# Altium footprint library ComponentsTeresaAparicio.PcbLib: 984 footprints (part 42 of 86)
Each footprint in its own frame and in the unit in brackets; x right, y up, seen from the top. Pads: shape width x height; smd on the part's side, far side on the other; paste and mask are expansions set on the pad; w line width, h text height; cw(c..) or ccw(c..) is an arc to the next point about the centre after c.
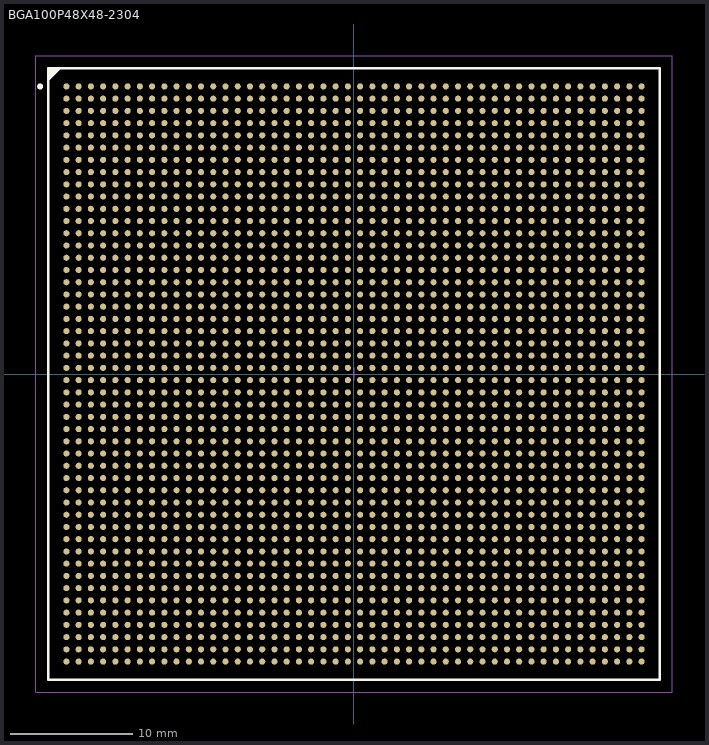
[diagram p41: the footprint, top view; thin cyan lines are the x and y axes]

## BGA100P48X48-2304 [mm] "BGA, 2304-Leads, Body 50x50mm, Pitch 1mm"
height 3.5
pads (2304):
  round 0.5 smd: A1(-23.5,23.5) A2(-22.5,23.5) A3(-21.5,23.5) A4(-20.5,23.5) A5(-19.5,23.5) A6(-18.5,23.5) A7(-17.5,23.5) A8(-16.5,23.5) A9(-15.5,23.5) A10(-14.5,23.5) A11(-13.5,23.5) A12(-12.5,23.5) A13(-11.5,23.5) A14(-10.5,23.5) A15(-9.5,23.5) A16(-8.5,23.5) A17(-7.5,23.5) A18(-6.5,23.5) A19(-5.5,23.5) A20(-4.5,23.5) A21(-3.5,23.5) A22(-2.5,23.5) A23(-1.5,23.5) A24(-0.5,23.5) A25(0.5,23.5) A26(1.5,23.5) A27(2.5,23.5) A28(3.5,23.5) A29(4.5,23.5) A30(5.5,23.5) A31(6.5,23.5) A32(7.5,23.5) A33(8.5,23.5) A34(9.5,23.5) A35(10.5,23.5) A36(11.5,23.5) A37(12.5,23.5) A38(13.5,23.5) A39(14.5,23.5) A40(15.5,23.5) A41(16.5,23.5) A42(17.5,23.5) A43(18.5,23.5) A44(19.5,23.5) A45(20.5,23.5) A46(21.5,23.5) A47(22.5,23.5) A48(23.5,23.5) AA1(-23.5,3.5) AA2(-22.5,3.5) AA3(-21.5,3.5) AA4(-20.5,3.5) AA5(-19.5,3.5) AA6(-18.5,3.5) AA7(-17.5,3.5) AA8(-16.5,3.5) AA9(-15.5,3.5) AA10(-14.5,3.5) AA11(-13.5,3.5) AA12(-12.5,3.5) AA13(-11.5,3.5) AA14(-10.5,3.5) AA15(-9.5,3.5) AA16(-8.5,3.5) AA17(-7.5,3.5) AA18(-6.5,3.5) AA19(-5.5,3.5) AA20(-4.5,3.5) AA21(-3.5,3.5) AA22(-2.5,3.5) AA23(-1.5,3.5) AA24(-0.5,3.5) AA25(0.5,3.5) AA26(1.5,3.5) AA27(2.5,3.5) AA28(3.5,3.5) AA29(4.5,3.5) AA30(5.5,3.5) AA31(6.5,3.5) AA32(7.5,3.5) AA33(8.5,3.5) AA34(9.5,3.5) AA35(10.5,3.5) AA36(11.5,3.5) AA37(12.5,3.5) AA38(13.5,3.5) AA39(14.5,3.5) AA40(15.5,3.5) AA41(16.5,3.5) AA42(17.5,3.5) AA43(18.5,3.5) AA44(19.5,3.5) AA45(20.5,3.5) AA46(21.5,3.5) AA47(22.5,3.5) AA48(23.5,3.5) AB1(-23.5,2.5) AB2(-22.5,2.5) AB3(-21.5,2.5) AB4(-20.5,2.5) AB5(-19.5,2.5) AB6(-18.5,2.5) AB7(-17.5,2.5) AB8(-16.5,2.5) AB9(-15.5,2.5) AB10(-14.5,2.5) AB11(-13.5,2.5) AB12(-12.5,2.5) AB13(-11.5,2.5) AB14(-10.5,2.5) AB15(-9.5,2.5) AB16(-8.5,2.5) AB17(-7.5,2.5) AB18(-6.5,2.5) AB19(-5.5,2.5) AB20(-4.5,2.5) AB21(-3.5,2.5) AB22(-2.5,2.5) AB23(-1.5,2.5) AB24(-0.5,2.5) AB25(0.5,2.5) AB26(1.5,2.5) AB27(2.5,2.5) AB28(3.5,2.5) AB29(4.5,2.5) AB30(5.5,2.5) AB31(6.5,2.5) AB32(7.5,2.5) AB33(8.5,2.5) AB34(9.5,2.5) AB35(10.5,2.5) AB36(11.5,2.5) AB37(12.5,2.5) AB38(13.5,2.5) AB39(14.5,2.5) AB40(15.5,2.5) AB41(16.5,2.5) AB42(17.5,2.5) AB43(18.5,2.5) AB44(19.5,2.5) AB45(20.5,2.5) AB46(21.5,2.5) AB47(22.5,2.5) AB48(23.5,2.5) AC1(-23.5,1.5) AC2(-22.5,1.5) AC3(-21.5,1.5) AC4(-20.5,1.5) AC5(-19.5,1.5) AC6(-18.5,1.5) AC7(-17.5,1.5) AC8(-16.5,1.5) AC9(-15.5,1.5) AC10(-14.5,1.5) AC11(-13.5,1.5) AC12(-12.5,1.5) AC13(-11.5,1.5) AC14(-10.5,1.5) AC15(-9.5,1.5) AC16(-8.5,1.5) AC17(-7.5,1.5) AC18(-6.5,1.5) AC19(-5.5,1.5) AC20(-4.5,1.5) AC21(-3.5,1.5) AC22(-2.5,1.5) AC23(-1.5,1.5) AC24(-0.5,1.5) AC25(0.5,1.5) AC26(1.5,1.5) AC27(2.5,1.5) AC28(3.5,1.5) AC29(4.5,1.5) AC30(5.5,1.5) AC31(6.5,1.5) AC32(7.5,1.5) AC33(8.5,1.5) AC34(9.5,1.5) AC35(10.5,1.5) AC36(11.5,1.5) AC37(12.5,1.5) AC38(13.5,1.5) AC39(14.5,1.5) AC40(15.5,1.5) AC41(16.5,1.5) AC42(17.5,1.5) AC43(18.5,1.5) AC44(19.5,1.5) AC45(20.5,1.5) AC46(21.5,1.5) AC47(22.5,1.5) AC48(23.5,1.5) AD1(-23.5,0.5) AD2(-22.5,0.5) AD3(-21.5,0.5) AD4(-20.5,0.5) AD5(-19.5,0.5) AD6(-18.5,0.5) AD7(-17.5,0.5) AD8(-16.5,0.5) AD9(-15.5,0.5) AD10(-14.5,0.5) AD11(-13.5,0.5) AD12(-12.5,0.5) AD13(-11.5,0.5) AD14(-10.5,0.5) AD15(-9.5,0.5) AD16(-8.5,0.5) AD17(-7.5,0.5) AD18(-6.5,0.5) AD19(-5.5,0.5) AD20(-4.5,0.5) AD21(-3.5,0.5) AD22(-2.5,0.5) AD23(-1.5,0.5) AD24(-0.5,0.5) AD25(0.5,0.5) AD26(1.5,0.5) AD27(2.5,0.5) AD28(3.5,0.5) AD29(4.5,0.5) AD30(5.5,0.5) AD31(6.5,0.5) AD32(7.5,0.5) AD33(8.5,0.5) AD34(9.5,0.5) AD35(10.5,0.5) AD36(11.5,0.5) AD37(12.5,0.5) AD38(13.5,0.5) AD39(14.5,0.5) AD40(15.5,0.5) AD41(16.5,0.5) AD42(17.5,0.5) AD43(18.5,0.5) AD44(19.5,0.5) AD45(20.5,0.5) AD46(21.5,0.5) AD47(22.5,0.5) AD48(23.5,0.5) AE1(-23.5,-0.5) AE2(-22.5,-0.5) AE3(-21.5,-0.5) AE4(-20.5,-0.5) AE5(-19.5,-0.5) AE6(-18.5,-0.5) AE7(-17.5,-0.5) AE8(-16.5,-0.5) AE9(-15.5,-0.5) AE10(-14.5,-0.5) AE11(-13.5,-0.5) AE12(-12.5,-0.5) AE13(-11.5,-0.5) AE14(-10.5,-0.5) AE15(-9.5,-0.5) AE16(-8.5,-0.5) AE17(-7.5,-0.5) AE18(-6.5,-0.5) AE19(-5.5,-0.5) AE20(-4.5,-0.5) AE21(-3.5,-0.5) AE22(-2.5,-0.5) AE23(-1.5,-0.5) AE24(-0.5,-0.5) AE25(0.5,-0.5) AE26(1.5,-0.5) AE27(2.5,-0.5) AE28(3.5,-0.5) AE29(4.5,-0.5) AE30(5.5,-0.5) AE31(6.5,-0.5) AE32(7.5,-0.5) AE33(8.5,-0.5) AE34(9.5,-0.5) AE35(10.5,-0.5) AE36(11.5,-0.5) AE37(12.5,-0.5) AE38(13.5,-0.5) AE39(14.5,-0.5) AE40(15.5,-0.5) AE41(16.5,-0.5) AE42(17.5,-0.5) AE43(18.5,-0.5) AE44(19.5,-0.5) AE45(20.5,-0.5) AE46(21.5,-0.5) AE47(22.5,-0.5) AE48(23.5,-0.5) AF1(-23.5,-1.5) AF2(-22.5,-1.5) AF3(-21.5,-1.5) AF4(-20.5,-1.5) AF5(-19.5,-1.5) AF6(-18.5,-1.5) AF7(-17.5,-1.5) AF8(-16.5,-1.5) AF9(-15.5,-1.5) AF10(-14.5,-1.5) AF11(-13.5,-1.5) AF12(-12.5,-1.5) AF13(-11.5,-1.5) AF14(-10.5,-1.5) AF15(-9.5,-1.5) AF16(-8.5,-1.5) AF17(-7.5,-1.5) AF18(-6.5,-1.5) AF19(-5.5,-1.5) AF20(-4.5,-1.5) AF21(-3.5,-1.5) AF22(-2.5,-1.5) AF23(-1.5,-1.5) AF24(-0.5,-1.5) AF25(0.5,-1.5) AF26(1.5,-1.5) AF27(2.5,-1.5) AF28(3.5,-1.5) AF29(4.5,-1.5) AF30(5.5,-1.5) AF31(6.5,-1.5) AF32(7.5,-1.5) AF33(8.5,-1.5) AF34(9.5,-1.5) AF35(10.5,-1.5) AF36(11.5,-1.5) AF37(12.5,-1.5) AF38(13.5,-1.5) AF39(14.5,-1.5) AF40(15.5,-1.5) AF41(16.5,-1.5) AF42(17.5,-1.5) AF43(18.5,-1.5) AF44(19.5,-1.5) AF45(20.5,-1.5) AF46(21.5,-1.5) AF47(22.5,-1.5) AF48(23.5,-1.5) AG1(-23.5,-2.5) AG2(-22.5,-2.5) AG3(-21.5,-2.5) AG4(-20.5,-2.5) AG5(-19.5,-2.5) AG6(-18.5,-2.5) AG7(-17.5,-2.5) AG8(-16.5,-2.5) AG9(-15.5,-2.5) AG10(-14.5,-2.5) AG11(-13.5,-2.5) AG12(-12.5,-2.5) AG13(-11.5,-2.5) AG14(-10.5,-2.5) AG15(-9.5,-2.5) AG16(-8.5,-2.5) AG17(-7.5,-2.5) AG18(-6.5,-2.5) AG19(-5.5,-2.5) AG20(-4.5,-2.5) AG21(-3.5,-2.5) AG22(-2.5,-2.5) AG23(-1.5,-2.5) AG24(-0.5,-2.5) AG25(0.5,-2.5) AG26(1.5,-2.5) AG27(2.5,-2.5) AG28(3.5,-2.5) AG29(4.5,-2.5) AG30(5.5,-2.5) AG31(6.5,-2.5) AG32(7.5,-2.5) AG33(8.5,-2.5) AG34(9.5,-2.5) AG35(10.5,-2.5) AG36(11.5,-2.5) AG37(12.5,-2.5) AG38(13.5,-2.5) AG39(14.5,-2.5) AG40(15.5,-2.5) AG41(16.5,-2.5) AG42(17.5,-2.5) AG43(18.5,-2.5) AG44(19.5,-2.5) AG45(20.5,-2.5) AG46(21.5,-2.5) AG47(22.5,-2.5) AG48(23.5,-2.5) AH1(-23.5,-3.5) AH2(-22.5,-3.5) AH3(-21.5,-3.5) AH4(-20.5,-3.5) AH5(-19.5,-3.5) AH6(-18.5,-3.5) AH7(-17.5,-3.5) AH8(-16.5,-3.5) AH9(-15.5,-3.5) AH10(-14.5,-3.5) AH11(-13.5,-3.5) AH12(-12.5,-3.5) AH13(-11.5,-3.5) AH14(-10.5,-3.5) AH15(-9.5,-3.5) AH16(-8.5,-3.5) AH17(-7.5,-3.5) AH18(-6.5,-3.5) AH19(-5.5,-3.5) AH20(-4.5,-3.5) AH21(-3.5,-3.5) AH22(-2.5,-3.5) AH23(-1.5,-3.5) AH24(-0.5,-3.5) AH25(0.5,-3.5) AH26(1.5,-3.5) AH27(2.5,-3.5) AH28(3.5,-3.5) AH29(4.5,-3.5) AH30(5.5,-3.5) AH31(6.5,-3.5) AH32(7.5,-3.5) AH33(8.5,-3.5) AH34(9.5,-3.5) AH35(10.5,-3.5) AH36(11.5,-3.5) AH37(12.5,-3.5) AH38(13.5,-3.5) AH39(14.5,-3.5) AH40(15.5,-3.5) AH41(16.5,-3.5) AH42(17.5,-3.5) AH43(18.5,-3.5) AH44(19.5,-3.5) AH45(20.5,-3.5) AH46(21.5,-3.5) AH47(22.5,-3.5) AH48(23.5,-3.5) AJ1(-23.5,-4.5) AJ2(-22.5,-4.5) AJ3(-21.5,-4.5) AJ4(-20.5,-4.5) AJ5(-19.5,-4.5) AJ6(-18.5,-4.5) AJ7(-17.5,-4.5) AJ8(-16.5,-4.5) AJ9(-15.5,-4.5) AJ10(-14.5,-4.5) AJ11(-13.5,-4.5) AJ12(-12.5,-4.5) AJ13(-11.5,-4.5) AJ14(-10.5,-4.5) AJ15(-9.5,-4.5) AJ16(-8.5,-4.5) AJ17(-7.5,-4.5) AJ18(-6.5,-4.5) AJ19(-5.5,-4.5) AJ20(-4.5,-4.5) AJ21(-3.5,-4.5) AJ22(-2.5,-4.5) AJ23(-1.5,-4.5) AJ24(-0.5,-4.5) AJ25(0.5,-4.5) AJ26(1.5,-4.5) AJ27(2.5,-4.5) AJ28(3.5,-4.5) AJ29(4.5,-4.5) AJ30(5.5,-4.5) AJ31(6.5,-4.5) AJ32(7.5,-4.5) AJ33(8.5,-4.5) AJ34(9.5,-4.5) AJ35(10.5,-4.5) AJ36(11.5,-4.5) AJ37(12.5,-4.5) AJ38(13.5,-4.5) AJ39(14.5,-4.5) AJ40(15.5,-4.5) AJ41(16.5,-4.5) AJ42(17.5,-4.5) AJ43(18.5,-4.5) AJ44(19.5,-4.5) AJ45(20.5,-4.5) AJ46(21.5,-4.5) AJ47(22.5,-4.5) AJ48(23.5,-4.5) AK1(-23.5,-5.5) AK2(-22.5,-5.5) AK3(-21.5,-5.5) AK4(-20.5,-5.5) AK5(-19.5,-5.5) AK6(-18.5,-5.5) AK7(-17.5,-5.5) AK8(-16.5,-5.5) AK9(-15.5,-5.5) AK10(-14.5,-5.5) AK11(-13.5,-5.5) AK12(-12.5,-5.5) AK13(-11.5,-5.5) AK14(-10.5,-5.5) AK15(-9.5,-5.5) AK16(-8.5,-5.5) AK17(-7.5,-5.5) AK18(-6.5,-5.5) AK19(-5.5,-5.5) AK20(-4.5,-5.5) AK21(-3.5,-5.5) AK22(-2.5,-5.5) AK23(-1.5,-5.5) AK24(-0.5,-5.5) AK25(0.5,-5.5) AK26(1.5,-5.5) AK27(2.5,-5.5) AK28(3.5,-5.5) AK29(4.5,-5.5) AK30(5.5,-5.5) AK31(6.5,-5.5) AK32(7.5,-5.5) AK33(8.5,-5.5) AK34(9.5,-5.5) AK35(10.5,-5.5) AK36(11.5,-5.5) AK37(12.5,-5.5) AK38(13.5,-5.5) AK39(14.5,-5.5) AK40(15.5,-5.5) AK41(16.5,-5.5) AK42(17.5,-5.5) AK43(18.5,-5.5) AK44(19.5,-5.5) AK45(20.5,-5.5) AK46(21.5,-5.5) AK47(22.5,-5.5) AK48(23.5,-5.5) AL1(-23.5,-6.5) AL2(-22.5,-6.5) AL3(-21.5,-6.5) AL4(-20.5,-6.5) AL5(-19.5,-6.5) AL6(-18.5,-6.5) AL7(-17.5,-6.5) AL8(-16.5,-6.5) AL9(-15.5,-6.5) AL10(-14.5,-6.5) AL11(-13.5,-6.5) AL12(-12.5,-6.5) AL13(-11.5,-6.5) AL14(-10.5,-6.5) AL15(-9.5,-6.5) AL16(-8.5,-6.5) AL17(-7.5,-6.5) AL18(-6.5,-6.5) AL19(-5.5,-6.5) AL20(-4.5,-6.5) AL21(-3.5,-6.5) AL22(-2.5,-6.5) AL23(-1.5,-6.5) AL24(-0.5,-6.5) AL25(0.5,-6.5) AL26(1.5,-6.5) AL27(2.5,-6.5) AL28(3.5,-6.5) AL29(4.5,-6.5) AL30(5.5,-6.5) AL31(6.5,-6.5) AL32(7.5,-6.5) AL33(8.5,-6.5) AL34(9.5,-6.5) AL35(10.5,-6.5) AL36(11.5,-6.5) AL37(12.5,-6.5) AL38(13.5,-6.5) AL39(14.5,-6.5) AL40(15.5,-6.5) AL41(16.5,-6.5) AL42(17.5,-6.5) AL43(18.5,-6.5) AL44(19.5,-6.5) AL45(20.5,-6.5) AL46(21.5,-6.5) AL47(22.5,-6.5) AL48(23.5,-6.5) AM1(-23.5,-7.5) AM2(-22.5,-7.5) AM3(-21.5,-7.5) AM4(-20.5,-7.5) AM5(-19.5,-7.5) AM6(-18.5,-7.5) AM7(-17.5,-7.5) AM8(-16.5,-7.5) AM9(-15.5,-7.5) AM10(-14.5,-7.5) AM11(-13.5,-7.5) AM12(-12.5,-7.5) AM13(-11.5,-7.5) AM14(-10.5,-7.5) AM15(-9.5,-7.5) AM16(-8.5,-7.5) AM17(-7.5,-7.5) AM18(-6.5,-7.5) AM19(-5.5,-7.5) AM20(-4.5,-7.5) AM21(-3.5,-7.5) AM22(-2.5,-7.5) AM23(-1.5,-7.5) AM24(-0.5,-7.5) AM25(0.5,-7.5) AM26(1.5,-7.5) AM27(2.5,-7.5) AM28(3.5,-7.5) AM29(4.5,-7.5) AM30(5.5,-7.5) AM31(6.5,-7.5) AM32(7.5,-7.5) AM33(8.5,-7.5) AM34(9.5,-7.5) AM35(10.5,-7.5) AM36(11.5,-7.5) AM37(12.5,-7.5) AM38(13.5,-7.5) AM39(14.5,-7.5) AM40(15.5,-7.5) AM41(16.5,-7.5) AM42(17.5,-7.5) AM43(18.5,-7.5) AM44(19.5,-7.5) AM45(20.5,-7.5) AM46(21.5,-7.5) AM47(22.5,-7.5) AM48(23.5,-7.5) AN1(-23.5,-8.5) AN2(-22.5,-8.5) AN3(-21.5,-8.5) AN4(-20.5,-8.5) AN5(-19.5,-8.5) AN6(-18.5,-8.5) AN7(-17.5,-8.5) AN8(-16.5,-8.5) AN9(-15.5,-8.5) AN10(-14.5,-8.5) AN11(-13.5,-8.5) AN12(-12.5,-8.5) AN13(-11.5,-8.5) AN14(-10.5,-8.5) AN15(-9.5,-8.5) AN16(-8.5,-8.5) AN17(-7.5,-8.5) AN18(-6.5,-8.5) AN19(-5.5,-8.5) AN20(-4.5,-8.5) AN21(-3.5,-8.5) AN22(-2.5,-8.5) AN23(-1.5,-8.5) AN24(-0.5,-8.5) AN25(0.5,-8.5) AN26(1.5,-8.5) AN27(2.5,-8.5) AN28(3.5,-8.5) AN29(4.5,-8.5) AN30(5.5,-8.5) AN31(6.5,-8.5) AN32(7.5,-8.5) AN33(8.5,-8.5) AN34(9.5,-8.5) AN35(10.5,-8.5) AN36(11.5,-8.5) AN37(12.5,-8.5) AN38(13.5,-8.5) AN39(14.5,-8.5) AN40(15.5,-8.5) AN41(16.5,-8.5) AN42(17.5,-8.5) AN43(18.5,-8.5) AN44(19.5,-8.5) AN45(20.5,-8.5) AN46(21.5,-8.5) AN47(22.5,-8.5) AN48(23.5,-8.5) AP1(-23.5,-9.5) AP2(-22.5,-9.5) AP3(-21.5,-9.5) AP4(-20.5,-9.5) AP5(-19.5,-9.5) AP6(-18.5,-9.5) AP7(-17.5,-9.5) AP8(-16.5,-9.5) AP9(-15.5,-9.5) AP10(-14.5,-9.5) AP11(-13.5,-9.5) AP12(-12.5,-9.5) AP13(-11.5,-9.5) AP14(-10.5,-9.5) AP15(-9.5,-9.5) AP16(-8.5,-9.5) AP17(-7.5,-9.5) AP18(-6.5,-9.5) AP19(-5.5,-9.5) AP20(-4.5,-9.5) AP21(-3.5,-9.5) AP22(-2.5,-9.5) AP23(-1.5,-9.5) AP24(-0.5,-9.5) AP25(0.5,-9.5) AP26(1.5,-9.5) AP27(2.5,-9.5) AP28(3.5,-9.5) AP29(4.5,-9.5) AP30(5.5,-9.5) AP31(6.5,-9.5) AP32(7.5,-9.5) AP33(8.5,-9.5) AP34(9.5,-9.5) AP35(10.5,-9.5) AP36(11.5,-9.5) AP37(12.5,-9.5) AP38(13.5,-9.5) AP39(14.5,-9.5) AP40(15.5,-9.5) AP41(16.5,-9.5) AP42(17.5,-9.5) AP43(18.5,-9.5) AP44(19.5,-9.5) AP45(20.5,-9.5) AP46(21.5,-9.5) AP47(22.5,-9.5) AP48(23.5,-9.5) AR1(-23.5,-10.5) AR2(-22.5,-10.5) AR3(-21.5,-10.5) AR4(-20.5,-10.5) AR5(-19.5,-10.5) AR6(-18.5,-10.5) AR7(-17.5,-10.5) AR8(-16.5,-10.5) AR9(-15.5,-10.5) AR10(-14.5,-10.5) AR11(-13.5,-10.5) AR12(-12.5,-10.5) AR13(-11.5,-10.5) AR14(-10.5,-10.5) AR15(-9.5,-10.5) AR16(-8.5,-10.5) AR17(-7.5,-10.5) AR18(-6.5,-10.5) AR19(-5.5,-10.5) AR20(-4.5,-10.5) AR21(-3.5,-10.5) AR22(-2.5,-10.5) AR23(-1.5,-10.5) AR24(-0.5,-10.5) AR25(0.5,-10.5) AR26(1.5,-10.5) AR27(2.5,-10.5) AR28(3.5,-10.5) AR29(4.5,-10.5) AR30(5.5,-10.5) AR31(6.5,-10.5) AR32(7.5,-10.5) AR33(8.5,-10.5) AR34(9.5,-10.5) AR35(10.5,-10.5) AR36(11.5,-10.5) AR37(12.5,-10.5) AR38(13.5,-10.5) AR39(14.5,-10.5) AR40(15.5,-10.5) AR41(16.5,-10.5) AR42(17.5,-10.5) AR43(18.5,-10.5) AR44(19.5,-10.5) AR45(20.5,-10.5) AR46(21.5,-10.5) AR47(22.5,-10.5) AR48(23.5,-10.5) AT1(-23.5,-11.5) AT2(-22.5,-11.5) AT3(-21.5,-11.5) AT4(-20.5,-11.5) AT5(-19.5,-11.5) AT6(-18.5,-11.5) AT7(-17.5,-11.5) AT8(-16.5,-11.5) AT9(-15.5,-11.5) AT10(-14.5,-11.5) AT11(-13.5,-11.5) AT12(-12.5,-11.5) AT13(-11.5,-11.5) AT14(-10.5,-11.5) AT15(-9.5,-11.5) AT16(-8.5,-11.5) AT17(-7.5,-11.5) AT18(-6.5,-11.5) AT19(-5.5,-11.5) AT20(-4.5,-11.5) AT21(-3.5,-11.5) AT22(-2.5,-11.5) AT23(-1.5,-11.5) AT24(-0.5,-11.5) AT25(0.5,-11.5) AT26(1.5,-11.5) AT27(2.5,-11.5) AT28(3.5,-11.5) AT29(4.5,-11.5) AT30(5.5,-11.5) AT31(6.5,-11.5) AT32(7.5,-11.5) AT33(8.5,-11.5) AT34(9.5,-11.5) AT35(10.5,-11.5) AT36(11.5,-11.5) AT37(12.5,-11.5) AT38(13.5,-11.5) AT39(14.5,-11.5) AT40(15.5,-11.5) AT41(16.5,-11.5) AT42(17.5,-11.5) AT43(18.5,-11.5) AT44(19.5,-11.5) AT45(20.5,-11.5) AT46(21.5,-11.5) AT47(22.5,-11.5) AT48(23.5,-11.5) AU1(-23.5,-12.5) AU2(-22.5,-12.5) AU3(-21.5,-12.5) AU4(-20.5,-12.5) AU5(-19.5,-12.5) AU6(-18.5,-12.5) AU7(-17.5,-12.5) AU8(-16.5,-12.5) AU9(-15.5,-12.5) AU10(-14.5,-12.5) AU11(-13.5,-12.5) AU12(-12.5,-12.5) AU13(-11.5,-12.5) AU14(-10.5,-12.5) AU15(-9.5,-12.5) AU16(-8.5,-12.5) AU17(-7.5,-12.5) AU18(-6.5,-12.5) AU19(-5.5,-12.5) AU20(-4.5,-12.5) AU21(-3.5,-12.5) AU22(-2.5,-12.5) AU23(-1.5,-12.5) AU24(-0.5,-12.5) AU25(0.5,-12.5) AU26(1.5,-12.5) AU27(2.5,-12.5) AU28(3.5,-12.5) AU29(4.5,-12.5) AU30(5.5,-12.5) AU31(6.5,-12.5) AU32(7.5,-12.5) AU33(8.5,-12.5) AU34(9.5,-12.5) AU35(10.5,-12.5) AU36(11.5,-12.5) AU37(12.5,-12.5) AU38(13.5,-12.5) AU39(14.5,-12.5) AU40(15.5,-12.5) AU41(16.5,-12.5) AU42(17.5,-12.5) AU43(18.5,-12.5) AU44(19.5,-12.5) AU45(20.5,-12.5) AU46(21.5,-12.5) AU47(22.5,-12.5) AU48(23.5,-12.5) AV1(-23.5,-13.5) AV2(-22.5,-13.5) AV3(-21.5,-13.5) AV4(-20.5,-13.5) AV5(-19.5,-13.5) AV6(-18.5,-13.5) AV7(-17.5,-13.5) AV8(-16.5,-13.5) AV9(-15.5,-13.5) AV10(-14.5,-13.5) AV11(-13.5,-13.5) AV12(-12.5,-13.5) AV13(-11.5,-13.5) AV14(-10.5,-13.5) AV15(-9.5,-13.5) AV16(-8.5,-13.5) AV17(-7.5,-13.5) AV18(-6.5,-13.5) AV19(-5.5,-13.5) AV20(-4.5,-13.5) AV21(-3.5,-13.5) AV22(-2.5,-13.5) AV23(-1.5,-13.5) AV24(-0.5,-13.5) AV25(0.5,-13.5) AV26(1.5,-13.5) AV27(2.5,-13.5) AV28(3.5,-13.5) AV29(4.5,-13.5) AV30(5.5,-13.5) AV31(6.5,-13.5) AV32(7.5,-13.5) AV33(8.5,-13.5) AV34(9.5,-13.5) AV35(10.5,-13.5) AV36(11.5,-13.5) AV37(12.5,-13.5) AV38(13.5,-13.5) AV39(14.5,-13.5) AV40(15.5,-13.5) AV41(16.5,-13.5) AV42(17.5,-13.5) AV43(18.5,-13.5) AV44(19.5,-13.5) AV45(20.5,-13.5) AV46(21.5,-13.5) AV47(22.5,-13.5) AV48(23.5,-13.5) AW1(-23.5,-14.5) AW2(-22.5,-14.5) AW3(-21.5,-14.5) AW4(-20.5,-14.5) AW5(-19.5,-14.5) AW6(-18.5,-14.5) AW7(-17.5,-14.5) AW8(-16.5,-14.5) AW9(-15.5,-14.5) AW10(-14.5,-14.5) AW11(-13.5,-14.5) AW12(-12.5,-14.5) AW13(-11.5,-14.5) AW14(-10.5,-14.5) AW15(-9.5,-14.5) AW16(-8.5,-14.5) AW17(-7.5,-14.5) AW18(-6.5,-14.5) AW19(-5.5,-14.5) AW20(-4.5,-14.5) AW21(-3.5,-14.5) AW22(-2.5,-14.5) AW23(-1.5,-14.5) AW24(-0.5,-14.5) AW25(0.5,-14.5) AW26(1.5,-14.5) AW27(2.5,-14.5) AW28(3.5,-14.5) AW29(4.5,-14.5) AW30(5.5,-14.5) AW31(6.5,-14.5) AW32(7.5,-14.5) AW33(8.5,-14.5) AW34(9.5,-14.5) AW35(10.5,-14.5) AW36(11.5,-14.5) AW37(12.5,-14.5) AW38(13.5,-14.5) AW39(14.5,-14.5) AW40(15.5,-14.5) AW41(16.5,-14.5) AW42(17.5,-14.5) AW43(18.5,-14.5) AW44(19.5,-14.5) AW45(20.5,-14.5) AW46(21.5,-14.5) AW47(22.5,-14.5) AW48(23.5,-14.5) AY1(-23.5,-15.5) AY2(-22.5,-15.5) AY3(-21.5,-15.5) AY4(-20.5,-15.5) AY5(-19.5,-15.5) AY6(-18.5,-15.5) AY7(-17.5,-15.5) AY8(-16.5,-15.5) AY9(-15.5,-15.5) AY10(-14.5,-15.5) AY11(-13.5,-15.5) AY12(-12.5,-15.5) AY13(-11.5,-15.5) AY14(-10.5,-15.5) AY15(-9.5,-15.5) AY16(-8.5,-15.5) AY17(-7.5,-15.5) AY18(-6.5,-15.5) AY19(-5.5,-15.5) AY20(-4.5,-15.5) AY21(-3.5,-15.5) AY22(-2.5,-15.5) AY23(-1.5,-15.5) AY24(-0.5,-15.5) AY25(0.5,-15.5) AY26(1.5,-15.5) AY27(2.5,-15.5) AY28(3.5,-15.5) AY29(4.5,-15.5) AY30(5.5,-15.5) AY31(6.5,-15.5) AY32(7.5,-15.5) AY33(8.5,-15.5) AY34(9.5,-15.5) AY35(10.5,-15.5) AY36(11.5,-15.5) AY37(12.5,-15.5) AY38(13.5,-15.5) AY39(14.5,-15.5) AY40(15.5,-15.5) AY41(16.5,-15.5) AY42(17.5,-15.5) AY43(18.5,-15.5) AY44(19.5,-15.5) AY45(20.5,-15.5) AY46(21.5,-15.5) AY47(22.5,-15.5) AY48(23.5,-15.5) B1(-23.5,22.5) B2(-22.5,22.5) B3(-21.5,22.5) B4(-20.5,22.5) B5(-19.5,22.5) B6(-18.5,22.5) B7(-17.5,22.5) B8(-16.5,22.5) B9(-15.5,22.5) B10(-14.5,22.5) B11(-13.5,22.5) B12(-12.5,22.5) B13(-11.5,22.5) B14(-10.5,22.5) B15(-9.5,22.5) B16(-8.5,22.5) B17(-7.5,22.5) B18(-6.5,22.5) B19(-5.5,22.5) B20(-4.5,22.5) B21(-3.5,22.5) B22(-2.5,22.5) B23(-1.5,22.5) B24(-0.5,22.5) B25(0.5,22.5) B26(1.5,22.5) B27(2.5,22.5) B28(3.5,22.5) B29(4.5,22.5) B30(5.5,22.5) B31(6.5,22.5) B32(7.5,22.5) B33(8.5,22.5) B34(9.5,22.5) B35(10.5,22.5) B36(11.5,22.5) B37(12.5,22.5) B38(13.5,22.5) B39(14.5,22.5) B40(15.5,22.5) B41(16.5,22.5) B42(17.5,22.5) B43(18.5,22.5) B44(19.5,22.5) B45(20.5,22.5) B46(21.5,22.5) B47(22.5,22.5) B48(23.5,22.5) BA1(-23.5,-16.5) BA2(-22.5,-16.5) BA3(-21.5,-16.5) BA4(-20.5,-16.5) BA5(-19.5,-16.5) BA6(-18.5,-16.5) BA7(-17.5,-16.5) BA8(-16.5,-16.5) BA9(-15.5,-16.5) BA10(-14.5,-16.5) BA11(-13.5,-16.5) BA12(-12.5,-16.5) BA13(-11.5,-16.5) BA14(-10.5,-16.5) BA15(-9.5,-16.5) BA16(-8.5,-16.5) BA17(-7.5,-16.5) BA18(-6.5,-16.5) BA19(-5.5,-16.5) BA20(-4.5,-16.5) BA21(-3.5,-16.5) BA22(-2.5,-16.5) BA23(-1.5,-16.5) BA24(-0.5,-16.5) BA25(0.5,-16.5) BA26(1.5,-16.5) BA27(2.5,-16.5) BA28(3.5,-16.5) BA29(4.5,-16.5) BA30(5.5,-16.5) BA31(6.5,-16.5) BA32(7.5,-16.5) BA33(8.5,-16.5) BA34(9.5,-16.5) BA35(10.5,-16.5) BA36(11.5,-16.5) BA37(12.5,-16.5) BA38(13.5,-16.5) BA39(14.5,-16.5) BA40(15.5,-16.5) BA41(16.5,-16.5) BA42(17.5,-16.5) BA43(18.5,-16.5) BA44(19.5,-16.5) BA45(20.5,-16.5) BA46(21.5,-16.5) BA47(22.5,-16.5) BA48(23.5,-16.5) BB1(-23.5,-17.5) BB2(-22.5,-17.5) BB3(-21.5,-17.5) BB4(-20.5,-17.5) BB5(-19.5,-17.5) BB6(-18.5,-17.5) BB7(-17.5,-17.5) BB8(-16.5,-17.5) BB9(-15.5,-17.5) BB10(-14.5,-17.5) BB11(-13.5,-17.5) BB12(-12.5,-17.5) BB13(-11.5,-17.5) BB14(-10.5,-17.5) BB15(-9.5,-17.5) BB16(-8.5,-17.5) BB17(-7.5,-17.5) BB18(-6.5,-17.5) BB19(-5.5,-17.5) BB20(-4.5,-17.5) BB21(-3.5,-17.5) BB22(-2.5,-17.5) BB23(-1.5,-17.5) BB24(-0.5,-17.5) BB25(0.5,-17.5) BB26(1.5,-17.5) BB27(2.5,-17.5) BB28(3.5,-17.5) BB29(4.5,-17.5) BB30(5.5,-17.5) BB31(6.5,-17.5) BB32(7.5,-17.5) BB33(8.5,-17.5) BB34(9.5,-17.5) BB35(10.5,-17.5) BB36(11.5,-17.5) BB37(12.5,-17.5) BB38(13.5,-17.5) BB39(14.5,-17.5) BB40(15.5,-17.5) BB41(16.5,-17.5) BB42(17.5,-17.5) BB43(18.5,-17.5) BB44(19.5,-17.5) BB45(20.5,-17.5) BB46(21.5,-17.5) BB47(22.5,-17.5) BB48(23.5,-17.5) BC1(-23.5,-18.5) BC2(-22.5,-18.5) BC3(-21.5,-18.5) BC4(-20.5,-18.5) BC5(-19.5,-18.5) BC6(-18.5,-18.5) BC7(-17.5,-18.5) BC8(-16.5,-18.5) BC9(-15.5,-18.5) BC10(-14.5,-18.5) BC11(-13.5,-18.5) BC12(-12.5,-18.5) BC13(-11.5,-18.5) BC14(-10.5,-18.5) BC15(-9.5,-18.5) BC16(-8.5,-18.5) BC17(-7.5,-18.5) BC18(-6.5,-18.5) BC19(-5.5,-18.5) BC20(-4.5,-18.5) BC21(-3.5,-18.5) BC22(-2.5,-18.5) BC23(-1.5,-18.5) BC24(-0.5,-18.5) BC25(0.5,-18.5) BC26(1.5,-18.5) BC27(2.5,-18.5) BC28(3.5,-18.5) BC29(4.5,-18.5) BC30(5.5,-18.5) BC31(6.5,-18.5) BC32(7.5,-18.5) BC33(8.5,-18.5) BC34(9.5,-18.5) BC35(10.5,-18.5) BC36(11.5,-18.5) BC37(12.5,-18.5) BC38(13.5,-18.5) BC39(14.5,-18.5) BC40(15.5,-18.5) BC41(16.5,-18.5) BC42(17.5,-18.5) BC43(18.5,-18.5) BC44(19.5,-18.5) BC45(20.5,-18.5) BC46(21.5,-18.5) BC47(22.5,-18.5) BC48(23.5,-18.5) BD1(-23.5,-19.5) BD2(-22.5,-19.5) BD3(-21.5,-19.5) BD4(-20.5,-19.5) BD5(-19.5,-19.5) BD6(-18.5,-19.5) BD7(-17.5,-19.5) BD8(-16.5,-19.5) BD9(-15.5,-19.5) BD10(-14.5,-19.5) BD11(-13.5,-19.5) BD12(-12.5,-19.5) BD13(-11.5,-19.5) BD14(-10.5,-19.5) BD15(-9.5,-19.5) BD16(-8.5,-19.5) BD17(-7.5,-19.5) BD18(-6.5,-19.5) BD19(-5.5,-19.5) BD20(-4.5,-19.5) BD21(-3.5,-19.5) BD22(-2.5,-19.5) BD23(-1.5,-19.5) BD24(-0.5,-19.5) BD25(0.5,-19.5) BD26(1.5,-19.5) BD27(2.5,-19.5) BD28(3.5,-19.5) BD29(4.5,-19.5) BD30(5.5,-19.5) BD31(6.5,-19.5) BD32(7.5,-19.5) BD33(8.5,-19.5) BD34(9.5,-19.5) BD35(10.5,-19.5) BD36(11.5,-19.5) BD37(12.5,-19.5) BD38(13.5,-19.5) BD39(14.5,-19.5) BD40(15.5,-19.5) BD41(16.5,-19.5) BD42(17.5,-19.5) BD43(18.5,-19.5) BD44(19.5,-19.5) BD45(20.5,-19.5) BD46(21.5,-19.5) BD47(22.5,-19.5) BD48(23.5,-19.5) BE1(-23.5,-20.5) BE2(-22.5,-20.5) BE3(-21.5,-20.5) BE4(-20.5,-20.5) BE5(-19.5,-20.5) BE6(-18.5,-20.5) BE7(-17.5,-20.5) BE8(-16.5,-20.5) BE9(-15.5,-20.5) BE10(-14.5,-20.5) BE11(-13.5,-20.5) BE12(-12.5,-20.5) BE13(-11.5,-20.5) BE14(-10.5,-20.5) BE15(-9.5,-20.5) BE16(-8.5,-20.5) BE17(-7.5,-20.5) BE18(-6.5,-20.5) BE19(-5.5,-20.5) BE20(-4.5,-20.5) BE21(-3.5,-20.5) BE22(-2.5,-20.5) BE23(-1.5,-20.5) BE24(-0.5,-20.5) BE25(0.5,-20.5) BE26(1.5,-20.5) BE27(2.5,-20.5) BE28(3.5,-20.5) BE29(4.5,-20.5) BE30(5.5,-20.5) BE31(6.5,-20.5) BE32(7.5,-20.5) BE33(8.5,-20.5) BE34(9.5,-20.5) BE35(10.5,-20.5) BE36(11.5,-20.5) BE37(12.5,-20.5) BE38(13.5,-20.5) BE39(14.5,-20.5) BE40(15.5,-20.5) BE41(16.5,-20.5) BE42(17.5,-20.5) BE43(18.5,-20.5) BE44(19.5,-20.5) BE45(20.5,-20.5) BE46(21.5,-20.5) BE47(22.5,-20.5) BE48(23.5,-20.5) BF1(-23.5,-21.5) BF2(-22.5,-21.5) BF3(-21.5,-21.5) BF4(-20.5,-21.5) BF5(-19.5,-21.5) BF6(-18.5,-21.5) BF7(-17.5,-21.5) BF8(-16.5,-21.5) BF9(-15.5,-21.5) BF10(-14.5,-21.5) BF11(-13.5,-21.5) BF12(-12.5,-21.5) BF13(-11.5,-21.5) BF14(-10.5,-21.5) BF15(-9.5,-21.5) BF16(-8.5,-21.5) BF17(-7.5,-21.5) BF18(-6.5,-21.5) BF19(-5.5,-21.5) BF20(-4.5,-21.5) BF21(-3.5,-21.5) BF22(-2.5,-21.5) BF23(-1.5,-21.5) BF24(-0.5,-21.5) BF25(0.5,-21.5) BF26(1.5,-21.5) BF27(2.5,-21.5) BF28(3.5,-21.5) BF29(4.5,-21.5) BF30(5.5,-21.5) BF31(6.5,-21.5) BF32(7.5,-21.5) BF33(8.5,-21.5) BF34(9.5,-21.5) BF35(10.5,-21.5) BF36(11.5,-21.5) BF37(12.5,-21.5) BF38(13.5,-21.5) BF39(14.5,-21.5) BF40(15.5,-21.5) BF41(16.5,-21.5) BF42(17.5,-21.5) BF43(18.5,-21.5) BF44(19.5,-21.5) BF45(20.5,-21.5) BF46(21.5,-21.5) BF47(22.5,-21.5) BF48(23.5,-21.5) BG1(-23.5,-22.5) BG2(-22.5,-22.5) BG3(-21.5,-22.5) BG4(-20.5,-22.5) BG5(-19.5,-22.5) BG6(-18.5,-22.5) BG7(-17.5,-22.5) BG8(-16.5,-22.5) BG9(-15.5,-22.5) BG10(-14.5,-22.5) BG11(-13.5,-22.5) BG12(-12.5,-22.5) BG13(-11.5,-22.5) BG14(-10.5,-22.5) BG15(-9.5,-22.5) BG16(-8.5,-22.5) BG17(-7.5,-22.5) BG18(-6.5,-22.5) BG19(-5.5,-22.5) BG20(-4.5,-22.5) BG21(-3.5,-22.5) BG22(-2.5,-22.5) BG23(-1.5,-22.5) BG24(-0.5,-22.5) BG25(0.5,-22.5) BG26(1.5,-22.5) BG27(2.5,-22.5) BG28(3.5,-22.5) BG29(4.5,-22.5) BG30(5.5,-22.5) BG31(6.5,-22.5) BG32(7.5,-22.5) BG33(8.5,-22.5) BG34(9.5,-22.5) BG35(10.5,-22.5) BG36(11.5,-22.5) BG37(12.5,-22.5) BG38(13.5,-22.5) BG39(14.5,-22.5) BG40(15.5,-22.5) BG41(16.5,-22.5) BG42(17.5,-22.5) BG43(18.5,-22.5) BG44(19.5,-22.5) BG45(20.5,-22.5) BG46(21.5,-22.5) BG47(22.5,-22.5) BG48(23.5,-22.5) BH1(-23.5,-23.5) BH2(-22.5,-23.5) BH3(-21.5,-23.5) BH4(-20.5,-23.5) BH5(-19.5,-23.5) BH6(-18.5,-23.5) BH7(-17.5,-23.5) BH8(-16.5,-23.5) BH9(-15.5,-23.5) BH10(-14.5,-23.5) BH11(-13.5,-23.5) BH12(-12.5,-23.5) BH13(-11.5,-23.5) BH14(-10.5,-23.5) BH15(-9.5,-23.5) BH16(-8.5,-23.5) BH17(-7.5,-23.5) BH18(-6.5,-23.5) BH19(-5.5,-23.5) BH20(-4.5,-23.5) BH21(-3.5,-23.5) BH22(-2.5,-23.5) BH23(-1.5,-23.5) BH24(-0.5,-23.5) BH25(0.5,-23.5) BH26(1.5,-23.5) BH27(2.5,-23.5) BH28(3.5,-23.5) BH29(4.5,-23.5) BH30(5.5,-23.5) BH31(6.5,-23.5) BH32(7.5,-23.5) BH33(8.5,-23.5) BH34(9.5,-23.5) BH35(10.5,-23.5) BH36(11.5,-23.5) BH37(12.5,-23.5) BH38(13.5,-23.5) BH39(14.5,-23.5) BH40(15.5,-23.5) BH41(16.5,-23.5) BH42(17.5,-23.5) BH43(18.5,-23.5) BH44(19.5,-23.5) BH45(20.5,-23.5) BH46(21.5,-23.5) BH47(22.5,-23.5) BH48(23.5,-23.5) C1(-23.5,21.5) C2(-22.5,21.5) C3(-21.5,21.5) C4(-20.5,21.5) C5(-19.5,21.5) C6(-18.5,21.5) C7(-17.5,21.5) C8(-16.5,21.5) C9(-15.5,21.5) C10(-14.5,21.5) C11(-13.5,21.5) C12(-12.5,21.5) C13(-11.5,21.5) C14(-10.5,21.5) C15(-9.5,21.5) C16(-8.5,21.5) C17(-7.5,21.5) C18(-6.5,21.5) C19(-5.5,21.5) C20(-4.5,21.5) C21(-3.5,21.5) C22(-2.5,21.5) C23(-1.5,21.5) C24(-0.5,21.5) C25(0.5,21.5) C26(1.5,21.5) C27(2.5,21.5) C28(3.5,21.5) C29(4.5,21.5) C30(5.5,21.5) C31(6.5,21.5) C32(7.5,21.5) C33(8.5,21.5) C34(9.5,21.5) C35(10.5,21.5) C36(11.5,21.5) C37(12.5,21.5) C38(13.5,21.5) C39(14.5,21.5) C40(15.5,21.5) C41(16.5,21.5) C42(17.5,21.5) C43(18.5,21.5) C44(19.5,21.5) C45(20.5,21.5) C46(21.5,21.5) C47(22.5,21.5) C48(23.5,21.5) D1(-23.5,20.5) D2(-22.5,20.5) D3(-21.5,20.5) D4(-20.5,20.5) D5(-19.5,20.5) D6(-18.5,20.5) D7(-17.5,20.5) D8(-16.5,20.5) D9(-15.5,20.5) D10(-14.5,20.5) D11(-13.5,20.5) D12(-12.5,20.5) D13(-11.5,20.5) D14(-10.5,20.5) D15(-9.5,20.5) D16(-8.5,20.5) D17(-7.5,20.5) D18(-6.5,20.5) D19(-5.5,20.5) D20(-4.5,20.5) D21(-3.5,20.5) D22(-2.5,20.5) D23(-1.5,20.5) D24(-0.5,20.5) D25(0.5,20.5) D26(1.5,20.5) D27(2.5,20.5) D28(3.5,20.5) D29(4.5,20.5) D30(5.5,20.5) D31(6.5,20.5) D32(7.5,20.5) D33(8.5,20.5) D34(9.5,20.5) D35(10.5,20.5) D36(11.5,20.5) D37(12.5,20.5) D38(13.5,20.5) D39(14.5,20.5) D40(15.5,20.5) D41(16.5,20.5) D42(17.5,20.5) D43(18.5,20.5) D44(19.5,20.5) D45(20.5,20.5) D46(21.5,20.5) D47(22.5,20.5) D48(23.5,20.5) E1(-23.5,19.5) E2(-22.5,19.5) E3(-21.5,19.5) E4(-20.5,19.5) E5(-19.5,19.5) E6(-18.5,19.5) E7(-17.5,19.5) E8(-16.5,19.5) E9(-15.5,19.5) E10(-14.5,19.5) E11(-13.5,19.5) E12(-12.5,19.5) E13(-11.5,19.5) E14(-10.5,19.5) E15(-9.5,19.5) E16(-8.5,19.5) E17(-7.5,19.5) E18(-6.5,19.5) E19(-5.5,19.5) E20(-4.5,19.5) E21(-3.5,19.5) E22(-2.5,19.5) E23(-1.5,19.5) E24(-0.5,19.5) E25(0.5,19.5) E26(1.5,19.5) E27(2.5,19.5) E28(3.5,19.5) E29(4.5,19.5) E30(5.5,19.5) E31(6.5,19.5) E32(7.5,19.5) E33(8.5,19.5) E34(9.5,19.5) E35(10.5,19.5) E36(11.5,19.5) E37(12.5,19.5) E38(13.5,19.5) E39(14.5,19.5) E40(15.5,19.5) E41(16.5,19.5) E42(17.5,19.5) E43(18.5,19.5) E44(19.5,19.5) E45(20.5,19.5) E46(21.5,19.5) E47(22.5,19.5) E48(23.5,19.5) F1(-23.5,18.5) F2(-22.5,18.5) F3(-21.5,18.5) F4(-20.5,18.5) F5(-19.5,18.5) F6(-18.5,18.5) F7(-17.5,18.5) F8(-16.5,18.5) F9(-15.5,18.5) F10(-14.5,18.5) F11(-13.5,18.5) F12(-12.5,18.5) F13(-11.5,18.5) F14(-10.5,18.5) F15(-9.5,18.5) F16(-8.5,18.5) F17(-7.5,18.5) F18(-6.5,18.5) F19(-5.5,18.5) F20(-4.5,18.5) F21(-3.5,18.5) F22(-2.5,18.5) F23(-1.5,18.5) F24(-0.5,18.5) F25(0.5,18.5) F26(1.5,18.5) F27(2.5,18.5) F28(3.5,18.5) F29(4.5,18.5) F30(5.5,18.5) F31(6.5,18.5) F32(7.5,18.5) F33(8.5,18.5) F34(9.5,18.5) F35(10.5,18.5) F36(11.5,18.5) F37(12.5,18.5) F38(13.5,18.5) F39(14.5,18.5) F40(15.5,18.5) F41(16.5,18.5) F42(17.5,18.5) F43(18.5,18.5) F44(19.5,18.5) F45(20.5,18.5) F46(21.5,18.5) F47(22.5,18.5) F48(23.5,18.5) G1(-23.5,17.5) G2(-22.5,17.5) G3(-21.5,17.5) G4(-20.5,17.5) G5(-19.5,17.5) G6(-18.5,17.5) G7(-17.5,17.5) G8(-16.5,17.5) G9(-15.5,17.5) G10(-14.5,17.5) G11(-13.5,17.5) G12(-12.5,17.5) G13(-11.5,17.5) G14(-10.5,17.5) G15(-9.5,17.5) G16(-8.5,17.5) G17(-7.5,17.5) G18(-6.5,17.5) G19(-5.5,17.5) G20(-4.5,17.5) G21(-3.5,17.5) G22(-2.5,17.5) G23(-1.5,17.5) G24(-0.5,17.5) G25(0.5,17.5) G26(1.5,17.5) G27(2.5,17.5) G28(3.5,17.5) G29(4.5,17.5) G30(5.5,17.5) G31(6.5,17.5) G32(7.5,17.5) G33(8.5,17.5) G34(9.5,17.5) G35(10.5,17.5) G36(11.5,17.5) G37(12.5,17.5) G38(13.5,17.5) G39(14.5,17.5) G40(15.5,17.5) G41(16.5,17.5) G42(17.5,17.5) G43(18.5,17.5) G44(19.5,17.5) G45(20.5,17.5) G46(21.5,17.5) G47(22.5,17.5) G48(23.5,17.5) H1(-23.5,16.5) H2(-22.5,16.5) H3(-21.5,16.5) H4(-20.5,16.5) H5(-19.5,16.5) H6(-18.5,16.5) H7(-17.5,16.5) H8(-16.5,16.5) H9(-15.5,16.5) H10(-14.5,16.5) H11(-13.5,16.5) H12(-12.5,16.5) H13(-11.5,16.5) H14(-10.5,16.5) H15(-9.5,16.5) H16(-8.5,16.5) H17(-7.5,16.5) H18(-6.5,16.5) H19(-5.5,16.5) H20(-4.5,16.5) H21(-3.5,16.5) H22(-2.5,16.5) H23(-1.5,16.5) H24(-0.5,16.5) H25(0.5,16.5) H26(1.5,16.5) H27(2.5,16.5) H28(3.5,16.5) H29(4.5,16.5) H30(5.5,16.5) H31(6.5,16.5) H32(7.5,16.5) H33(8.5,16.5) H34(9.5,16.5) H35(10.5,16.5) H36(11.5,16.5) H37(12.5,16.5) H38(13.5,16.5) H39(14.5,16.5) H40(15.5,16.5) H41(16.5,16.5) H42(17.5,16.5) H43(18.5,16.5) H44(19.5,16.5) H45(20.5,16.5) H46(21.5,16.5) H47(22.5,16.5) H48(23.5,16.5) J1(-23.5,15.5) J2(-22.5,15.5) J3(-21.5,15.5) J4(-20.5,15.5) J5(-19.5,15.5) J6(-18.5,15.5) J7(-17.5,15.5) J8(-16.5,15.5) J9(-15.5,15.5) J10(-14.5,15.5) J11(-13.5,15.5) J12(-12.5,15.5) J13(-11.5,15.5) J14(-10.5,15.5) J15(-9.5,15.5) J16(-8.5,15.5) J17(-7.5,15.5) J18(-6.5,15.5) J19(-5.5,15.5) J20(-4.5,15.5) J21(-3.5,15.5) J22(-2.5,15.5) J23(-1.5,15.5) J24(-0.5,15.5) J25(0.5,15.5) J26(1.5,15.5) J27(2.5,15.5) J28(3.5,15.5) J29(4.5,15.5) J30(5.5,15.5) J31(6.5,15.5) J32(7.5,15.5) J33(8.5,15.5) J34(9.5,15.5) J35(10.5,15.5) J36(11.5,15.5) J37(12.5,15.5) J38(13.5,15.5) J39(14.5,15.5) J40(15.5,15.5) J41(16.5,15.5) J42(17.5,15.5) J43(18.5,15.5) J44(19.5,15.5) J45(20.5,15.5) J46(21.5,15.5) J47(22.5,15.5) J48(23.5,15.5) K1(-23.5,14.5) K2(-22.5,14.5) K3(-21.5,14.5) K4(-20.5,14.5) K5(-19.5,14.5) K6(-18.5,14.5) K7(-17.5,14.5) K8(-16.5,14.5) K9(-15.5,14.5) K10(-14.5,14.5) K11(-13.5,14.5) K12(-12.5,14.5) K13(-11.5,14.5) K14(-10.5,14.5) K15(-9.5,14.5) K16(-8.5,14.5) K17(-7.5,14.5) K18(-6.5,14.5) K19(-5.5,14.5) K20(-4.5,14.5) K21(-3.5,14.5) K22(-2.5,14.5) K23(-1.5,14.5) K24(-0.5,14.5) K25(0.5,14.5) K26(1.5,14.5) K27(2.5,14.5) K28(3.5,14.5) K29(4.5,14.5) K30(5.5,14.5) K31(6.5,14.5) K32(7.5,14.5) K33(8.5,14.5) K34(9.5,14.5) K35(10.5,14.5) K36(11.5,14.5) K37(12.5,14.5) K38(13.5,14.5) K39(14.5,14.5) K40(15.5,14.5) K41(16.5,14.5) K42(17.5,14.5) K43(18.5,14.5) K44(19.5,14.5) K45(20.5,14.5) K46(21.5,14.5) K47(22.5,14.5) K48(23.5,14.5) L1(-23.5,13.5) L2(-22.5,13.5) L3(-21.5,13.5) L4(-20.5,13.5) L5(-19.5,13.5) L6(-18.5,13.5) L7(-17.5,13.5) L8(-16.5,13.5) L9(-15.5,13.5) L10(-14.5,13.5) L11(-13.5,13.5) L12(-12.5,13.5) L13(-11.5,13.5) L14(-10.5,13.5) L15(-9.5,13.5) L16(-8.5,13.5) L17(-7.5,13.5) L18(-6.5,13.5) L19(-5.5,13.5) L20(-4.5,13.5) L21(-3.5,13.5) L22(-2.5,13.5) L23(-1.5,13.5) L24(-0.5,13.5) L25(0.5,13.5) L26(1.5,13.5) L27(2.5,13.5) L28(3.5,13.5) L29(4.5,13.5) L30(5.5,13.5) L31(6.5,13.5) L32(7.5,13.5) L33(8.5,13.5) L34(9.5,13.5) L35(10.5,13.5) L36(11.5,13.5) L37(12.5,13.5) L38(13.5,13.5) L39(14.5,13.5) L40(15.5,13.5) L41(16.5,13.5) L42(17.5,13.5) L43(18.5,13.5) L44(19.5,13.5) L45(20.5,13.5) L46(21.5,13.5) L47(22.5,13.5) L48(23.5,13.5) M1(-23.5,12.5) M2(-22.5,12.5) M3(-21.5,12.5) M4(-20.5,12.5) M5(-19.5,12.5) M6(-18.5,12.5) M7(-17.5,12.5) M8(-16.5,12.5) M9(-15.5,12.5) M10(-14.5,12.5) M11(-13.5,12.5) M12(-12.5,12.5) M13(-11.5,12.5) M14(-10.5,12.5) M15(-9.5,12.5) M16(-8.5,12.5) M17(-7.5,12.5) M18(-6.5,12.5) M19(-5.5,12.5) M20(-4.5,12.5) M21(-3.5,12.5) M22(-2.5,12.5) M23(-1.5,12.5) M24(-0.5,12.5) M25(0.5,12.5) M26(1.5,12.5) M27(2.5,12.5) M28(3.5,12.5) M29(4.5,12.5) M30(5.5,12.5) M31(6.5,12.5) M32(7.5,12.5) M33(8.5,12.5) M34(9.5,12.5) M35(10.5,12.5) M36(11.5,12.5) M37(12.5,12.5) M38(13.5,12.5) M39(14.5,12.5) M40(15.5,12.5) M41(16.5,12.5) M42(17.5,12.5) M43(18.5,12.5) M44(19.5,12.5) M45(20.5,12.5) M46(21.5,12.5) M47(22.5,12.5) M48(23.5,12.5) N1(-23.5,11.5) N2(-22.5,11.5) N3(-21.5,11.5) N4(-20.5,11.5) N5(-19.5,11.5) N6(-18.5,11.5) N7(-17.5,11.5) N8(-16.5,11.5) N9(-15.5,11.5) N10(-14.5,11.5) N11(-13.5,11.5) N12(-12.5,11.5) N13(-11.5,11.5) N14(-10.5,11.5) N15(-9.5,11.5) N16(-8.5,11.5) N17(-7.5,11.5) N18(-6.5,11.5) N19(-5.5,11.5) N20(-4.5,11.5) N21(-3.5,11.5) N22(-2.5,11.5) N23(-1.5,11.5) N24(-0.5,11.5) N25(0.5,11.5) N26(1.5,11.5) N27(2.5,11.5) N28(3.5,11.5) N29(4.5,11.5) N30(5.5,11.5) N31(6.5,11.5) N32(7.5,11.5) N33(8.5,11.5) N34(9.5,11.5) N35(10.5,11.5) N36(11.5,11.5) N37(12.5,11.5) N38(13.5,11.5) N39(14.5,11.5) N40(15.5,11.5) N41(16.5,11.5) N42(17.5,11.5) N43(18.5,11.5) N44(19.5,11.5) N45(20.5,11.5) N46(21.5,11.5) N47(22.5,11.5) N48(23.5,11.5) P1(-23.5,10.5) P2(-22.5,10.5) P3(-21.5,10.5) P4(-20.5,10.5) P5(-19.5,10.5) P6(-18.5,10.5) P7(-17.5,10.5) P8(-16.5,10.5) P9(-15.5,10.5) P10(-14.5,10.5) P11(-13.5,10.5) P12(-12.5,10.5) P13(-11.5,10.5) P14(-10.5,10.5) P15(-9.5,10.5) P16(-8.5,10.5) P17(-7.5,10.5) P18(-6.5,10.5) P19(-5.5,10.5) P20(-4.5,10.5) P21(-3.5,10.5) P22(-2.5,10.5) P23(-1.5,10.5) P24(-0.5,10.5) P25(0.5,10.5) P26(1.5,10.5) P27(2.5,10.5) P28(3.5,10.5) P29(4.5,10.5) P30(5.5,10.5) P31(6.5,10.5) P32(7.5,10.5) P33(8.5,10.5) P34(9.5,10.5) P35(10.5,10.5) P36(11.5,10.5) P37(12.5,10.5) P38(13.5,10.5) P39(14.5,10.5) P40(15.5,10.5) P41(16.5,10.5) P42(17.5,10.5) P43(18.5,10.5) P44(19.5,10.5) P45(20.5,10.5) P46(21.5,10.5) P47(22.5,10.5) P48(23.5,10.5) R1(-23.5,9.5) R2(-22.5,9.5) R3(-21.5,9.5) R4(-20.5,9.5) R5(-19.5,9.5) R6(-18.5,9.5) R7(-17.5,9.5) R8(-16.5,9.5) R9(-15.5,9.5) R10(-14.5,9.5) R11(-13.5,9.5) R12(-12.5,9.5) R13(-11.5,9.5) R14(-10.5,9.5) R15(-9.5,9.5) R16(-8.5,9.5) R17(-7.5,9.5) R18(-6.5,9.5) R19(-5.5,9.5) R20(-4.5,9.5) R21(-3.5,9.5) R22(-2.5,9.5) R23(-1.5,9.5) R24(-0.5,9.5) R25(0.5,9.5) R26(1.5,9.5) R27(2.5,9.5) R28(3.5,9.5) R29(4.5,9.5) R30(5.5,9.5) R31(6.5,9.5) R32(7.5,9.5) R33(8.5,9.5) R34(9.5,9.5) R35(10.5,9.5) R36(11.5,9.5) R37(12.5,9.5) R38(13.5,9.5) R39(14.5,9.5) R40(15.5,9.5) R41(16.5,9.5) R42(17.5,9.5) R43(18.5,9.5) R44(19.5,9.5) R45(20.5,9.5) R46(21.5,9.5) R47(22.5,9.5) R48(23.5,9.5) T1(-23.5,8.5) T2(-22.5,8.5) T3(-21.5,8.5) T4(-20.5,8.5) T5(-19.5,8.5) T6(-18.5,8.5) T7(-17.5,8.5) T8(-16.5,8.5) T9(-15.5,8.5) T10(-14.5,8.5) T11(-13.5,8.5) T12(-12.5,8.5) T13(-11.5,8.5) T14(-10.5,8.5) T15(-9.5,8.5) T16(-8.5,8.5) T17(-7.5,8.5) T18(-6.5,8.5) T19(-5.5,8.5) T20(-4.5,8.5) T21(-3.5,8.5) T22(-2.5,8.5) T23(-1.5,8.5) T24(-0.5,8.5) T25(0.5,8.5) T26(1.5,8.5) T27(2.5,8.5) T28(3.5,8.5) T29(4.5,8.5) T30(5.5,8.5) T31(6.5,8.5) T32(7.5,8.5) T33(8.5,8.5) T34(9.5,8.5) T35(10.5,8.5) T36(11.5,8.5) T37(12.5,8.5) T38(13.5,8.5) T39(14.5,8.5) T40(15.5,8.5) T41(16.5,8.5) T42(17.5,8.5) T43(18.5,8.5) T44(19.5,8.5) T45(20.5,8.5) T46(21.5,8.5) T47(22.5,8.5) T48(23.5,8.5) U1(-23.5,7.5) U2(-22.5,7.5) U3(-21.5,7.5) U4(-20.5,7.5) U5(-19.5,7.5) U6(-18.5,7.5) U7(-17.5,7.5) U8(-16.5,7.5) U9(-15.5,7.5) U10(-14.5,7.5) U11(-13.5,7.5) U12(-12.5,7.5) U13(-11.5,7.5) U14(-10.5,7.5) U15(-9.5,7.5) U16(-8.5,7.5) U17(-7.5,7.5) U18(-6.5,7.5) U19(-5.5,7.5) U20(-4.5,7.5) U21(-3.5,7.5) U22(-2.5,7.5) U23(-1.5,7.5) U24(-0.5,7.5) U25(0.5,7.5) U26(1.5,7.5) U27(2.5,7.5) U28(3.5,7.5) U29(4.5,7.5) U30(5.5,7.5) U31(6.5,7.5) U32(7.5,7.5) U33(8.5,7.5) U34(9.5,7.5) U35(10.5,7.5) U36(11.5,7.5) U37(12.5,7.5) U38(13.5,7.5) U39(14.5,7.5) U40(15.5,7.5) U41(16.5,7.5) U42(17.5,7.5) U43(18.5,7.5) U44(19.5,7.5) U45(20.5,7.5) U46(21.5,7.5) U47(22.5,7.5) U48(23.5,7.5) V1(-23.5,6.5) V2(-22.5,6.5) V3(-21.5,6.5) V4(-20.5,6.5) V5(-19.5,6.5) V6(-18.5,6.5) V7(-17.5,6.5) V8(-16.5,6.5) V9(-15.5,6.5) V10(-14.5,6.5) V11(-13.5,6.5) V12(-12.5,6.5) V13(-11.5,6.5) V14(-10.5,6.5) V15(-9.5,6.5) V16(-8.5,6.5) V17(-7.5,6.5) V18(-6.5,6.5) V19(-5.5,6.5) V20(-4.5,6.5) V21(-3.5,6.5) V22(-2.5,6.5) V23(-1.5,6.5) V24(-0.5,6.5) V25(0.5,6.5) V26(1.5,6.5) V27(2.5,6.5) V28(3.5,6.5) V29(4.5,6.5) V30(5.5,6.5) V31(6.5,6.5) V32(7.5,6.5) V33(8.5,6.5) V34(9.5,6.5) V35(10.5,6.5) V36(11.5,6.5) V37(12.5,6.5) V38(13.5,6.5) V39(14.5,6.5) V40(15.5,6.5) V41(16.5,6.5) V42(17.5,6.5) V43(18.5,6.5) V44(19.5,6.5) V45(20.5,6.5) V46(21.5,6.5) V47(22.5,6.5) V48(23.5,6.5) W1(-23.5,5.5) W2(-22.5,5.5) W3(-21.5,5.5) W4(-20.5,5.5) W5(-19.5,5.5) W6(-18.5,5.5) W7(-17.5,5.5) W8(-16.5,5.5) W9(-15.5,5.5) W10(-14.5,5.5) W11(-13.5,5.5) W12(-12.5,5.5) W13(-11.5,5.5) W14(-10.5,5.5) W15(-9.5,5.5) W16(-8.5,5.5) W17(-7.5,5.5) W18(-6.5,5.5) W19(-5.5,5.5) W20(-4.5,5.5) W21(-3.5,5.5) W22(-2.5,5.5) W23(-1.5,5.5) W24(-0.5,5.5) W25(0.5,5.5) W26(1.5,5.5) W27(2.5,5.5) W28(3.5,5.5) W29(4.5,5.5) W30(5.5,5.5) W31(6.5,5.5) W32(7.5,5.5) W33(8.5,5.5) W34(9.5,5.5) W35(10.5,5.5) W36(11.5,5.5) W37(12.5,5.5) W38(13.5,5.5) W39(14.5,5.5) W40(15.5,5.5) W41(16.5,5.5) W42(17.5,5.5) W43(18.5,5.5) W44(19.5,5.5) W45(20.5,5.5) W46(21.5,5.5) W47(22.5,5.5) W48(23.5,5.5) Y1(-23.5,4.5) Y2(-22.5,4.5) Y3(-21.5,4.5) Y4(-20.5,4.5) Y5(-19.5,4.5) Y6(-18.5,4.5) Y7(-17.5,4.5) Y8(-16.5,4.5) Y9(-15.5,4.5) Y10(-14.5,4.5) Y11(-13.5,4.5) Y12(-12.5,4.5) Y13(-11.5,4.5) Y14(-10.5,4.5) Y15(-9.5,4.5) Y16(-8.5,4.5) Y17(-7.5,4.5) Y18(-6.5,4.5) Y19(-5.5,4.5) Y20(-4.5,4.5) Y21(-3.5,4.5) Y22(-2.5,4.5) Y23(-1.5,4.5) Y24(-0.5,4.5) Y25(0.5,4.5) Y26(1.5,4.5) Y27(2.5,4.5) Y28(3.5,4.5) Y29(4.5,4.5) Y30(5.5,4.5) Y31(6.5,4.5) Y32(7.5,4.5) Y33(8.5,4.5) Y34(9.5,4.5) Y35(10.5,4.5) Y36(11.5,4.5) Y37(12.5,4.5) Y38(13.5,4.5) Y39(14.5,4.5) Y40(15.5,4.5) Y41(16.5,4.5) Y42(17.5,4.5) Y43(18.5,4.5) Y44(19.5,4.5) Y45(20.5,4.5) Y46(21.5,4.5) Y47(22.5,4.5) Y48(23.5,4.5)
Top Overlay:
  circle w0.25: c-25.65,23.5 r0.125
  region: -24,25 -25,24 -25,25
  lines w0.2: -25,24 -24,25 ; -25,-25 25,-25 25,25 -25,25 -25,-25
Mechanical 13:
  lines w0.1: -25,-25 25,-25 25,25 -25,25 -25,-25
Mechanical 15:
  lines w0.1: -0.5,0 0.5,0 ; 0,-0.5 0,0.5 ; -26,-26 26,-26 26,26 -26,26 -26,-26
3D body: height 0, standoff 0, extent -25,-25 25,25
